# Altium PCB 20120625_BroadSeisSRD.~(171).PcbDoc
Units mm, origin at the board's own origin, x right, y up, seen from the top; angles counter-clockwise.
Board outline 68.5 x 51 mm, 4 copper layers (Top Layer, Mid-Layer 1, Mid-Layer 2, Bottom Layer); 59 components, 42 nets, 186 pads, 37 vias.
Unrouted connection lines stored in the file: 1.
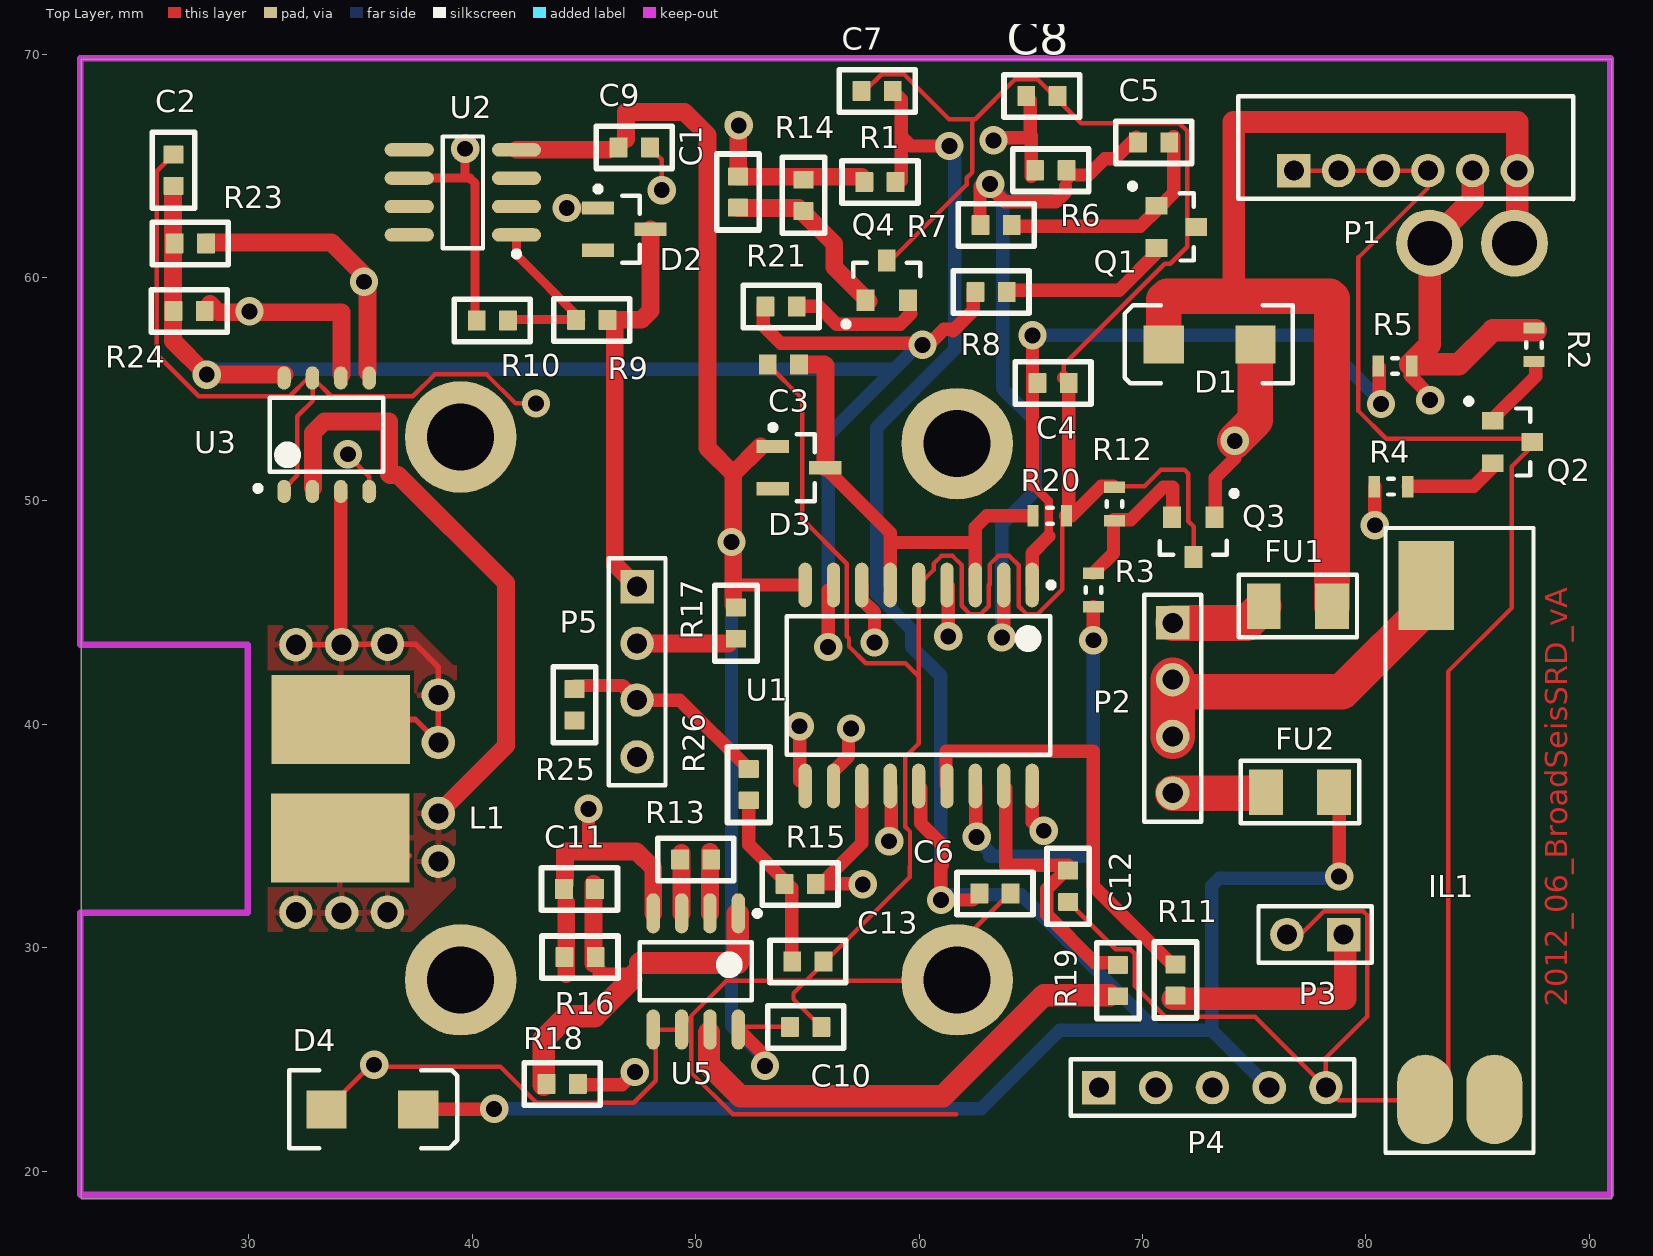
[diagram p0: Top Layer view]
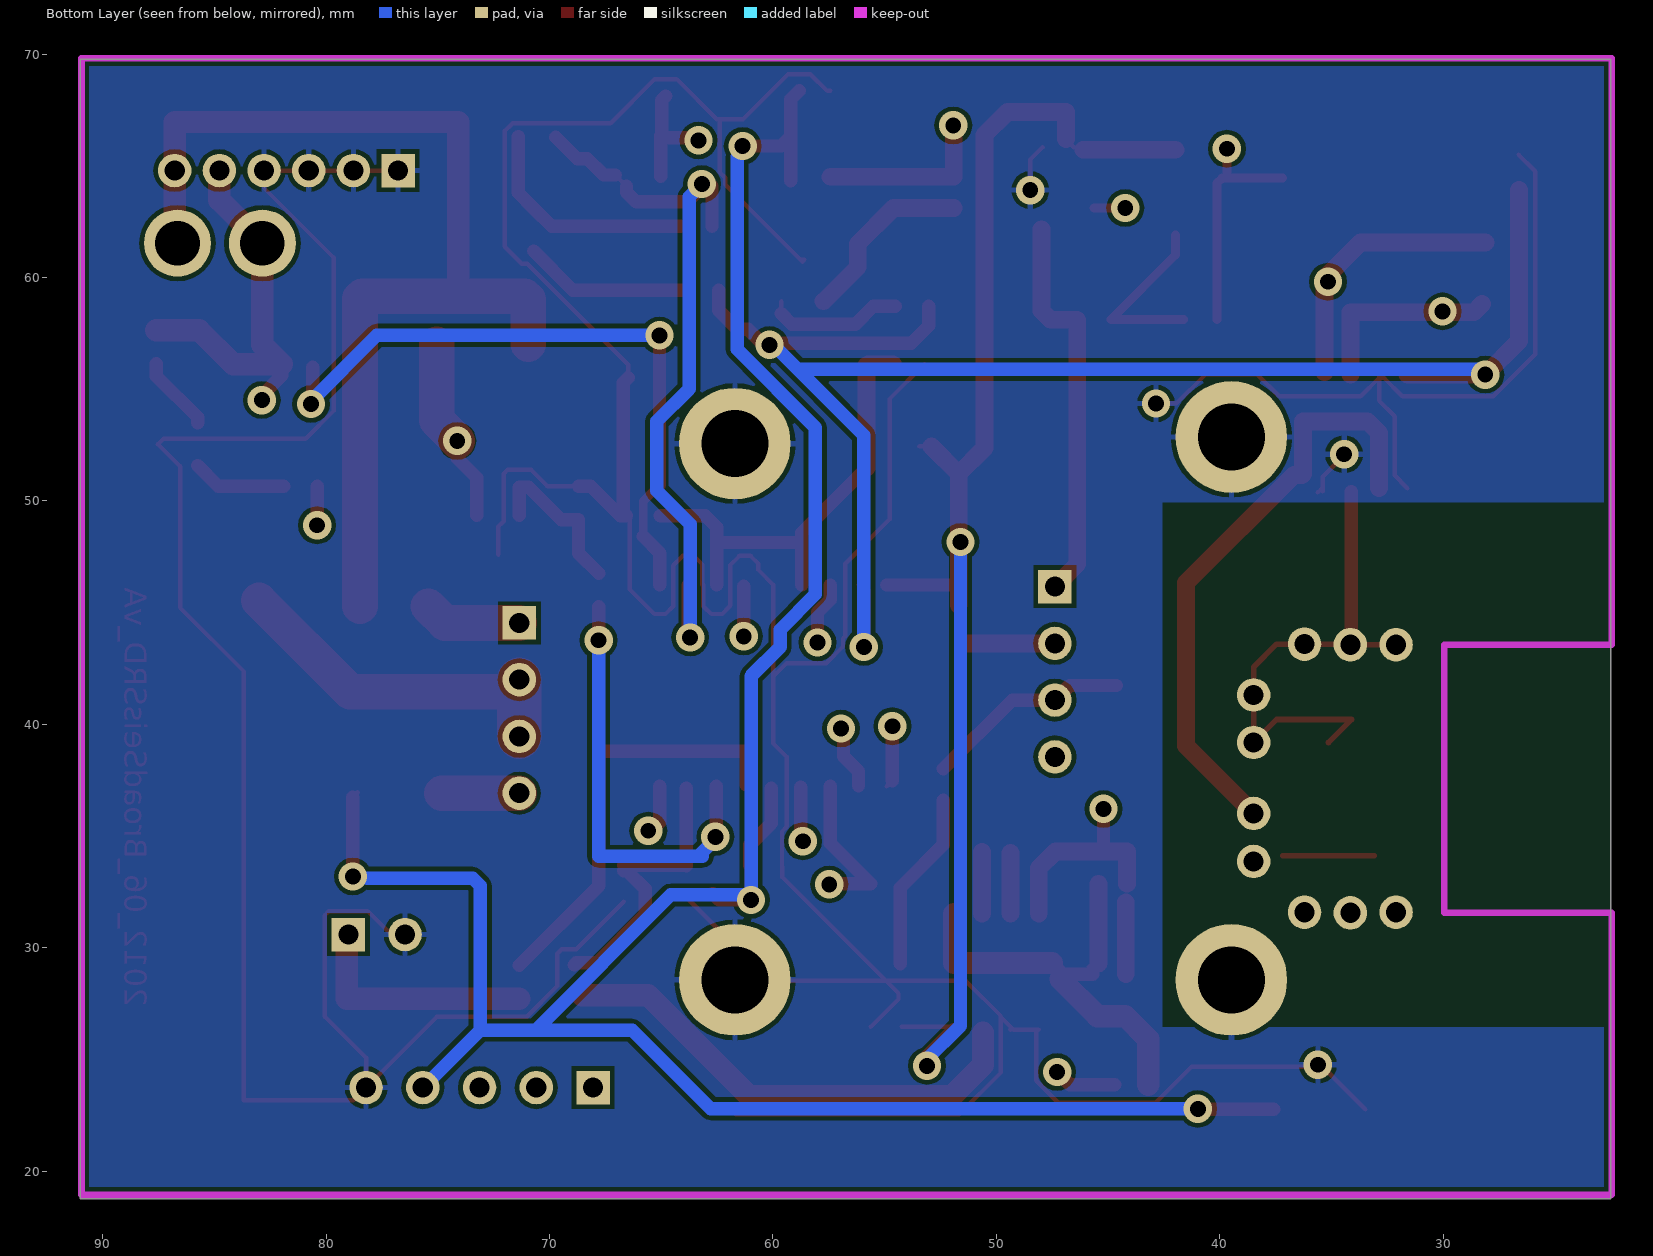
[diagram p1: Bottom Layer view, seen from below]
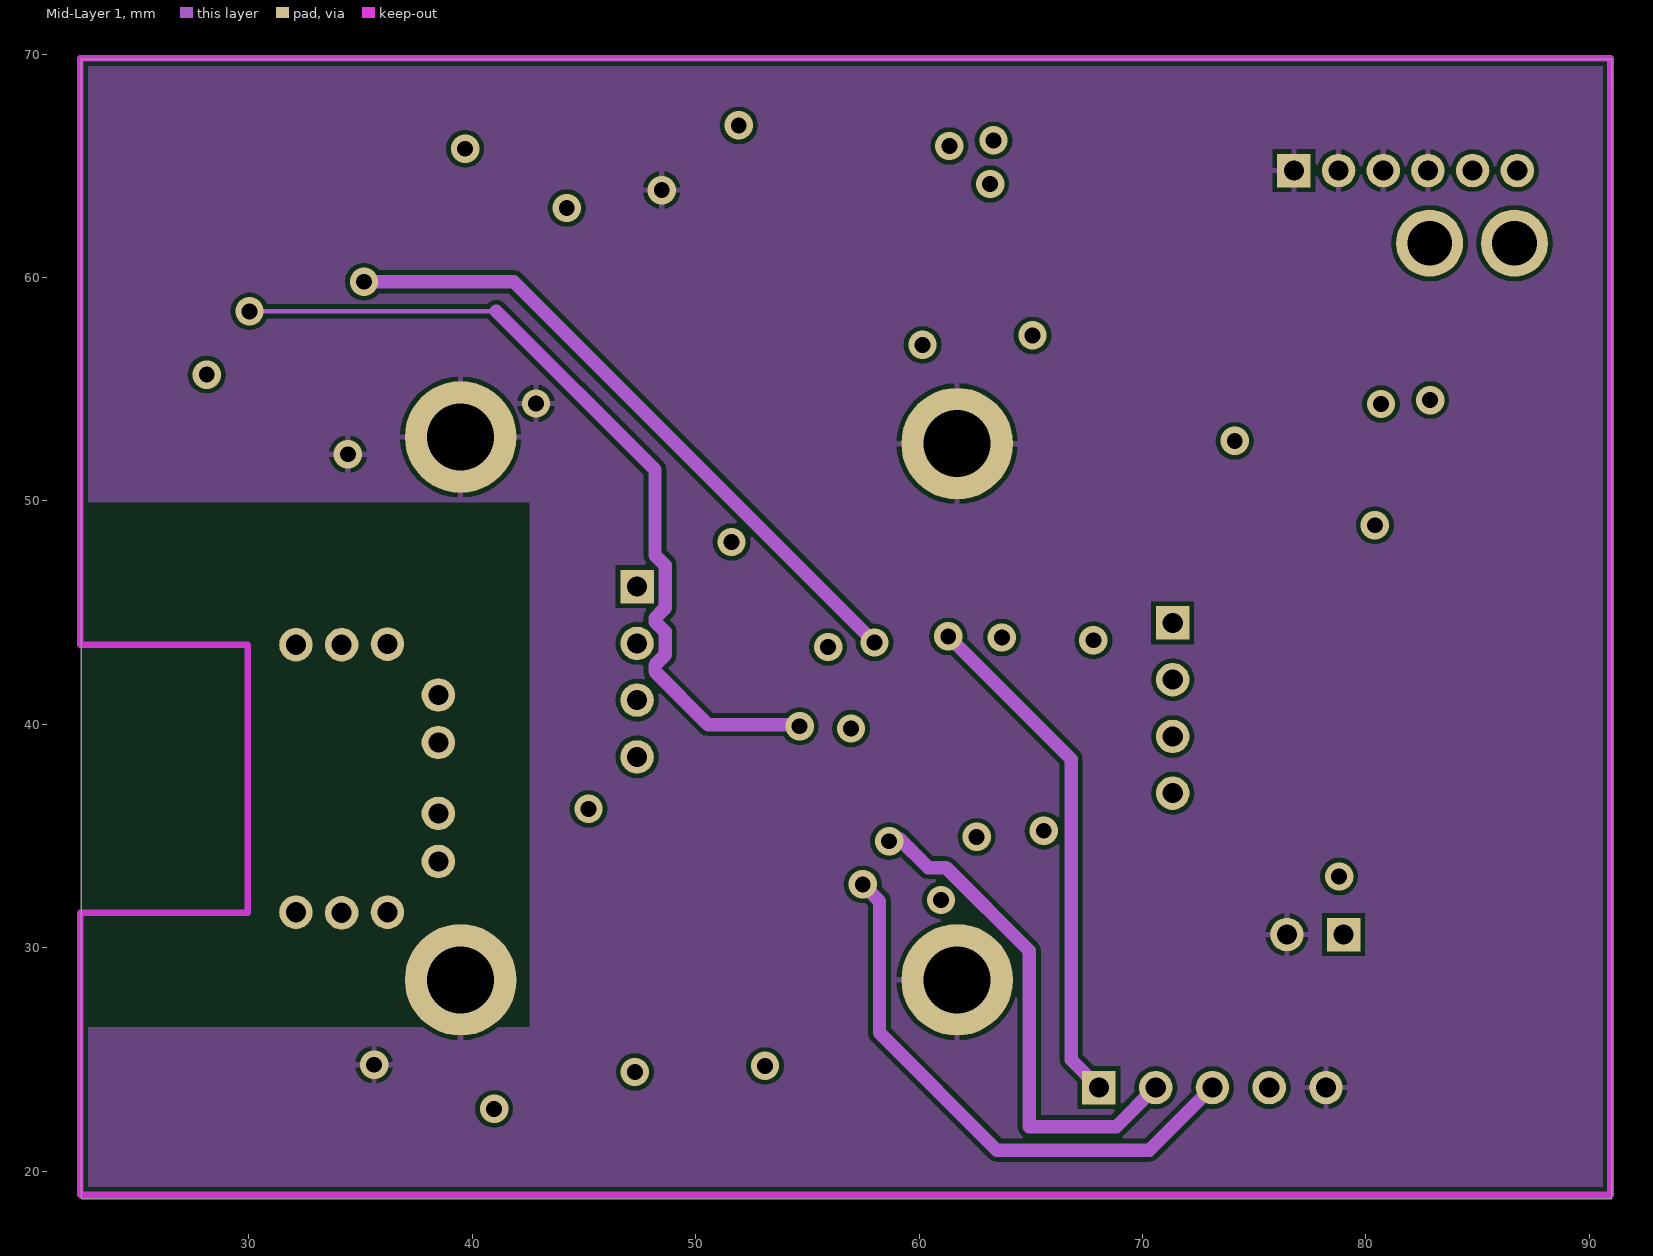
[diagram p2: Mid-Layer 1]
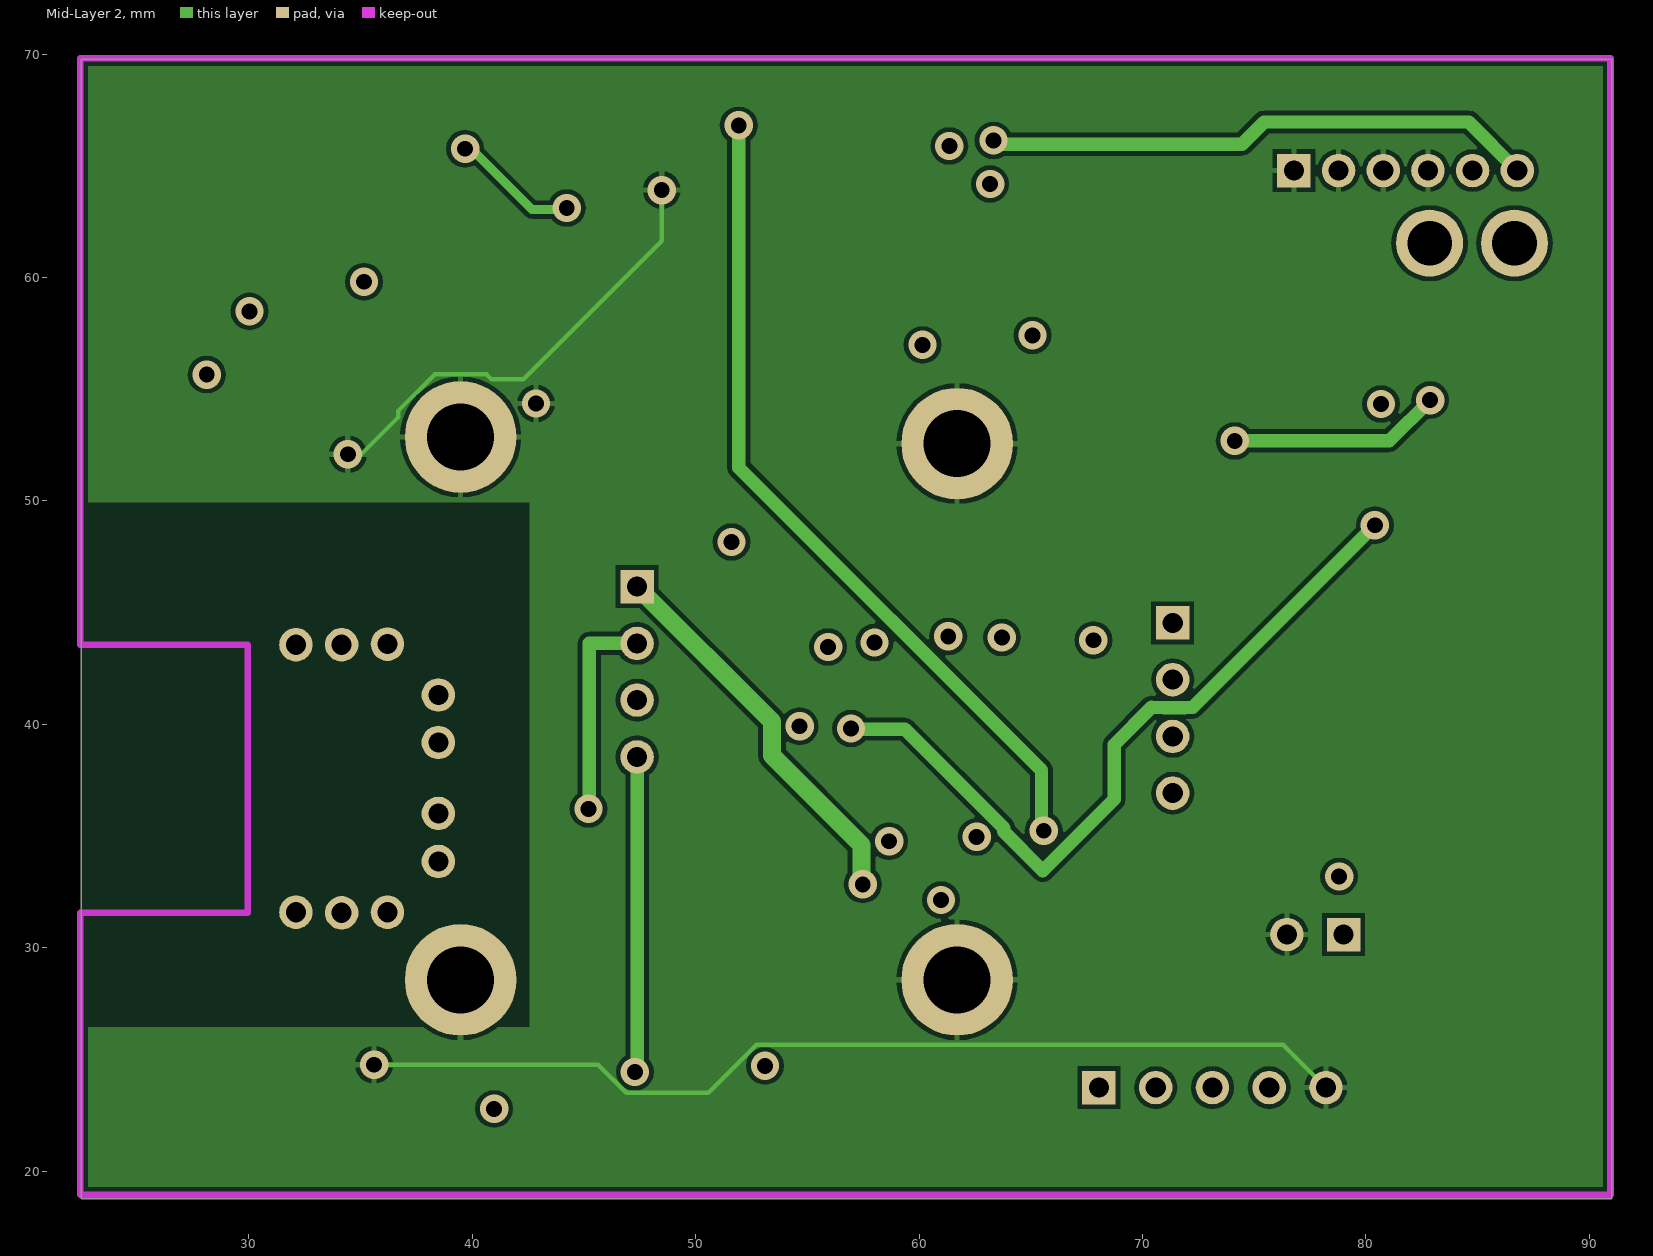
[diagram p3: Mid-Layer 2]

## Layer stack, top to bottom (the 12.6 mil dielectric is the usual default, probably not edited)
Top Layer: signal copper 0.0356
Dielectric: dielectric 0.32, FR-4, Dk 4.8
Mid-Layer 1: signal copper 0.0356
Dielectric: dielectric 0.32, FR-4, Dk 4.8
Mid-Layer 2: signal copper 0.0356
Dielectric: dielectric 0.32, FR-4, Dk 4.8
Bottom Layer: signal copper 0.0356

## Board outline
22.505,18.76 91.005,18.76 91.005,69.76 22.505,69.76

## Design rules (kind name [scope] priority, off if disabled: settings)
Clearance [All] p1: gap=0.2
HoleSize [All] p1: absolutevalues=TRUE maxlimit=5 minlimit=0.025 maxpercent=80.000 minpercent=20.000
PolygonConnect [All] p1: connectstyle=Relief reliefconductorwidth=0.254 reliefentries=4 polygonreliefangle="90 Angle"
RoomDefinition 2012_06_22_Sheet [InComponentClass('2012_06_22_Sheet')] p1: confinementstyle=ConfineIn formatcopy=TRUE lockcomponents=FALSE outline 20.986,71.285 21.117,71.153 93.055,71.153 93.055,17.297 92.819,17.06 20.855,17.06
RoutingVias [All] p1: holewidth=0.6 width=1 viastyle="Through Hole" minholewidth=0.711 minwidth=1.27 maxholewidth=0.711 maxwidth=1.27
SilkscreenOverComponentPads [All] p1: minsilkscreentomaskgap=0.254
SolderMaskExpansion [All] p1: expansion=0.102
Width [All] p1: maxlimit=2 minlimit=0.2 preferedwidth=0.6
26 further rules are at their usual default settings.

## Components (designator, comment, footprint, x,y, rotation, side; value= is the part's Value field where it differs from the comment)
C1 "Cap Semi" 1608[0603]#1 51.9,63.825 r90 top
C2 "Cap Semi" 1608[0603]#1 26.625,64.8 r270 top
C3 "Cap Semi" 1608[0603]#2 53.93,56.11 r0 top
C4 "Cap Semi" 1608[0603]#1 66,55.275 r180 top
C5 "Cap Semi" 1608[0603]#1 70.5,66.05 r180 top
C6 "Cap Semi" 1608[0603]#1 63.4,32.425 r180 top
C7 "Cap Semi" 1608[0603]#1 58.125,68.35 r0 top
C8 "Cap Semi" 1608[0603]#1 65.5,68.125 r180 top
C9 "Cap Semi" 1608[0603]#1 47.25,65.825 r180 top
C10 "Cap Semi" 1608[0603]#1 54.925,26.45 r180 top
C11 "Cap Semi" 1608[0603]#1 44.8,32.625 r180 top
C12 "Cap Semi" 1608[0603]#1 66.675,32.75 r90 top
C13 "Cap Semi" 1608[0603]#1 55.025,29.375 r180 top
D1 "RS1D" DiodeRS1D(recommendedfootprint) 73.005,57.01 r180 top
D2 "Diode BAS16" SOT-23_M 46.805,62.16 r0 top
D3 "Diode BAS16" SOT-23_M 54.63,51.485 r0 top
D4 "RS1D" DiodeRS1D(recommendedfootprint) 35.53,22.76 r0 top
FU1 "1A" FU(recommendedfootprint) 76.955,45.285 r0 top
FU2 "200mA" FU(recommendedfootprint) 77.055,36.96 r180 top
IL1 "ILS" ILS 85.655,46.21 r270 top
L1 "Inductor" INDC4532 34.105,37.56 r270 top
P1 "ConnectorToFB" "HIROSE DF3A-6P" 76.78,64.785 r0 top
P2 "Battery Pack pigtail" HDR1X4 71.355,44.535 r270 top
P3 "Connector to LED" HDR1X2 79.005,30.585 r180 top
P4 "Connector to Prog." HDR1X5 68.055,23.735 r0 top
P5 "Pressure Transducer pigtail" HDR1X4 47.38,46.16 r270 top
Q1 "NPN" transistor_SOT-23(recommendedfootprint) 71.605,62.26 r0 top
Q2 "NPN" transistor_SOT-23(recommendedfootprint) 86.655,52.635 r0 top
Q3 "MOSFET-IRLML" transistor_SOT-23(recommendedfootprint) 72.28,48.285 r270 top
Q4 "NPN" transistor_SOT-23(recommendedfootprint) 58.555,59.96 r90 top
R1 "Res3" J1-0603#1 58.25,64.275 r0 top
R2 "Res3" J1-0603#2 87.53,56.985 r90 top
R3 "Res3" J1-0603#2 67.805,46.01 r90 top
R4 "Res3" J1-0603#2 81.13,50.635 r0 top
R5 "Res3" J1-0603#2 81.305,56.035 r0 top
R6 "Res3" J1-0603#1 65.9,64.8 r180 top
R7 "Res3" J1-0603#1 63.45,62.35 r180 top
R8 "Res3" J1-0603#1 63.225,59.35 r0 top
R9 "Res3" J1-0603#1 45.35,58.1 r0 top
R10 "Res3" J1-0603#1 40.9,58.075 r180 top
R11 "Res3" J1-0603#1 71.475,28.55 r90 top
R12 "Res3" J1-0603#2 68.755,49.86 r270 top
R13 "Res3" J1-0603#1 50,33.95 r0 top
R14 "Res3" J1-0603#1 54.825,63.675 r90 top
R15 "Res3" J1-0603#1 54.675,32.85 r180 top
R16 "Res3" J1-0603#1 44.825,29.575 r180 top
R17 "Res3" J1-0603#1 51.8,44.525 r90 top
R18 "Res3" 1608[0603]#1 44.025,23.9 r180 top
R19 "Res3" J1-0603#1 68.9,28.525 r90 top
R20 "Res3" J1-0603#2 65.855,49.335 r180 top
R21 "Res3" J1-0603#1 53.825,58.7 r0 top
R23 "Res3" J1-0603#1 27.375,61.525 r0 top
R24 "Res3" J1-0603#1 27.325,58.5 r180 top
R25 "Res3" J1-0603#1 44.575,40.875 r90 top
R26 "Res3" J1-0603#1 52.375,37.3 r90 top
U1 "PIC16LF1827-I/SO" SOIC-SO18_L 59.98,41.735 r270 top
U2 "LM334D" SO8_N 39.58,63.81 r180 top
U3 "M24LR64" SO8N_N 33.48,52.96 r90 top
U5 "AD620BR" R-8D_N 50.005,28.935 r270 top

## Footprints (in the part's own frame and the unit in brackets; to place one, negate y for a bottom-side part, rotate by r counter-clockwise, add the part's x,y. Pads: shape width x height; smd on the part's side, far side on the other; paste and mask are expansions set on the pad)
1608[0603]#1 [mm] "Chip Capacitor, Body 1.6x0.8mm, IPC High Density"
  rrect10% 0.8x0.9 smd: 1(-0.7,0) 2(0.7,0)
  silkscreen extent -1.7,-0.95 1.7,0.95
1608[0603]#2 [mm] "Chip Capacitor, Body 1.6x0.8mm, IPC High Density"
  rect 0.8x0.9 smd: 1(-0.7,0) 2(0.7,0)
  body extent -0.87,-0.48 0.87,0.48, height 1.3
DiodeRS1D(recommendedfootprint) [mm] "DO-214-AB/SMC; 2 C-Bend Leads; Body 7.9 x 5.9 mm, inc. leads (LxW)"
  rect 1.8x1.7 smd: 1(-2.05,0) 2(2.05,0)
  silkscreen extent -3.73,-1.75 3.8,1.75
FU(recommendedfootprint) [mm] "Thru-Hole; 2 Leads"
  rect 1.52x2.03 smd: 1(-1.525,0) 2(1.525,0)
  silkscreen extent -2.65,-1.4 2.65,1.4
HDR1X2 [mm] "Connector; Header; 2 Position"
  rect 1.5x1.5 hole 0.9: 1(0,0)
  round 1.5 hole 0.9: 2(2.54,0)
  silkscreen extent -1.27,-1.27 3.81,1.27
HDR1X4 [mm] "Connector; Header; 4 Position"
  rect 1.5x1.5 hole 0.9: 1(0,0)
  round 1.5 hole 0.9: 2(2.54,0) 3(5.08,0) 4(7.62,0)
  silkscreen extent -1.27,-1.27 8.89,1.27
HDR1X5 [mm] "Connector; Header; 5 Position"
  rect 1.5x1.5 hole 0.9: 1(0,0)
  round 1.5 hole 0.9: 2(2.54,0) 3(5.08,0) 4(7.62,0) 5(10.16,0)
  silkscreen extent -1.27,-1.27 11.43,1.27
"HIROSE DF3A-6P" [mm] "Connector; Header; 6 Position"
  rect 1.5x1.5 hole 0.9: 1(0,0)
  round 1.5 hole 0.9: 2(2,0) 3(4,0) 4(6,0) 5(8,0) 6(10,0)
  round 3 hole 2: 5(6.075,-3.25) 6(9.875,-3.25)
  Top Layer lines w0.254: 9.875,-3.25 10,-2.75
  Top Layer lines w1: 6.075,-3.25 8,-1.325 8,0 ; 10,-2.75 10,0
  silkscreen extent -2.5,-1.29 12.5,3.32
ILS [mm]
  rect 4x2.5 smd: 1(0,-2.95)
  oval 4x2.5 smd: 2(23,-3) 3(23,0.1)
  silkscreen extent -2.58,-4.77 25.4,1.85
INDC4532 [mm] "Chip Inductor, Body 4.5x3.2mm, IPC High Density"
  round 1.5 hole 0.9: 1(-6.025,2.1) 1(-6,0.05) 1(-6,-2) 1(-3.75,4.375) 1(-1.625,4.375) 2(1.55,4.375) 2(3.7,4.375) 2(5.975,2.1) 2(5.975,-2) 2(6,0.05)
  rect 4x6.2 smd: 1(-2.65,0) 2(2.65,-0.025)
  Top Layer lines w0.254: -6,-2 -6,0.01 -6,0.05 -6.025,0.075 -6.025,2.1 -6.025,3.35 -5,4.375 -3.75,4.375 -1.625,4.375 -2.65,3.35 -2.65,0 -1.625,1.025
J1-0603#1 [mm] "Chip Capacitor, Body 1.6x0.8mm, IPC High Density"
  rrect10% 0.8x0.9 smd: 1(-0.7,0) 2(0.7,0)
  silkscreen extent -1.7,-0.95 1.7,0.95
J1-0603#2 [mm] "Chip Resistor, Body 1.6x0.8mm, IPC High Density"
  rect 0.5x0.95 smd: 1(-0.75,0) 2(0.75,0)
  silkscreen extent -0.13,-0.35 0.13,0.35, body extent -0.85,-0.48 0.85,0.48, height 0.9
R-8D_N [mm] "SOIC, 8-Leads, Body 4.9x3.9mm, Pitch 1.27mm, IPC Medium Density"
  oval 1.8x0.6 smd: 1(-2.6,1.905) 2(-2.6,0.635) 3(-2.6,-0.635) 4(-2.6,-1.905) 5(2.6,-1.905) 6(2.6,-0.635) 7(2.6,0.635) 8(2.6,1.905)
  silkscreen extent -2.72,-2.5 1.3,2.88, body extent -2,-2.5 2,2.5, height 2.59
SO8_N [mm] "SOIC, 8-Leads, Body 4.9x3.9mm, Pitch 1.27mm, IPC Medium Density"
  oval 2.2x0.6 smd: 1(-2.4,1.905) 2(-2.4,0.635) 3(-2.4,-0.635) 4(-2.4,-1.905) 5(2.4,-1.905) 6(2.4,-0.635) 7(2.4,0.635) 8(2.4,1.905)
  silkscreen extent -2.53,-2.5 0.9,2.88, body extent -1.95,-2.45 1.95,2.45, height 1.75
SO8N_N [mm] "SOP, 8-Leads, Body 5.3x5.3mm, Pitch 1.27mm, IPC Medium Density"
  oval 1.04x0.6 smd: 1(-2.54,1.905) 2(-2.54,0.635) 3(-2.54,-0.635) 4(-2.54,-1.905) 5(2.54,-1.905) 6(2.54,-0.635) 7(2.54,0.635) 8(2.54,1.905)
  silkscreen extent -2.52,-2.54 1.65,3.2, body extent -2.29,-2.54 2.29,2.54, height 2.13
SOIC-SO18_L [mm] "SOIC, 18-Leads, Body 11.5x7.5mm, Pitch 1.27mm, IPC High Density"
  oval 2x0.6 smd: 1(-4.5,5.08) 2(-4.5,3.81) 3(-4.5,2.54) 4(-4.5,1.27) 5(-4.5,0) 6(-4.5,-1.27) 7(-4.5,-2.54) 8(-4.5,-3.81) 9(-4.5,-5.08) 10(4.5,-5.08) 11(4.5,-3.81) 12(4.5,-2.54) 13(4.5,-1.27) 14(4.5,0) 15(4.5,1.27) 16(4.5,2.54) 17(4.5,3.81) 18(4.5,5.08)
  silkscreen extent -4.62,-5.9 3.1,6.06, body extent -3.8,-5.95 3.8,5.95, height 2.65
SOT-23_M [mm] "SOT23, 3-Leads, Body 2.9x1.3mm, Pitch 0.95mm, Lead Span 2.5mm, IPC Low Density"
  rect 1.45x0.6 smd: 1(-1.175,0.95) 2(-1.175,-0.95) 3(1.175,0)
  silkscreen extent -1.3,-1.5 0.7,1.92, body extent -0.7,-1.5 0.7,1.5, height 1.1
transistor_SOT-23(recommendedfootprint) [mm] "SOT23, 3-Leads, Body 2.9x1.3mm, Pitch 0.95mm, Lead Span 2.5mm, IPC Low Density"
  rect 0.972x0.802 smd: 1(-0.975,0.95) 2(-0.975,-0.95) 3(0.8,0)
  silkscreen extent -2.17,-1.5 0.7,1.95, body extent -0.7,-1.5 0.7,1.5, height 1.1

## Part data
C1 C2 C3 C4 C5 C6 C7 C8 C9 C10 C11 C12 C13: "Capacitor (Semiconductor SIM Model)"
D1 D4: library part Diode, "Default Diode"
D2 D3: "Silicon Switching Diode for High-Speed Switching"
FU1 FU2: library part "Fuse 1", "Fuse"
IL1: "SPDT Subminiature Toggle Switch, Right Angle Mounting, Vertical Actuation"
P1: "Header, 6-Pin"
P2 P5: "Header, 4-Pin"
P3: "Header, 2-Pin"
P4: "Header, 5-Pin"
Q1 Q2 Q4: "NPN Bipolar Transistor"
Q3: "N-Channel MOSFET"
R1 R2 R3 R4 R5 R6 R7 R8 R9 R10 R11 R12 R13 R14 R15 R16 R17 R18 R19 R20 R21 R23 R24 R25 R26: "Resistor"
U1: "EPROM-Based 8-Bit CMOS Microcontroller, 25 Bytes RAM, 4 MHz, 18-Pin SOIC, 3.0 to 5.5V Supply Range, Extended Temperature"
U2: "Three Terminal Adjustable Current Source"
U3: "32 Kbit Serial I²C Bus EEPROM"
U5: "Low-Cost, Low-Power Instrumentation Amplifier"

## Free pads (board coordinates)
  round 5 hole 3: 1(39.48,28.56) 1(39.48,52.86) 1(61.705,28.56) 1(61.705,52.56)

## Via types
v1: diameter 1.27, hole 0.711, Top Layer to Bottom Layer, 37 vias

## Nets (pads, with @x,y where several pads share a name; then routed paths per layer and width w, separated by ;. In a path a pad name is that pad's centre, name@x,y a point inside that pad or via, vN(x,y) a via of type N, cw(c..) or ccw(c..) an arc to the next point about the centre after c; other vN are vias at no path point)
ACTIVATION+: FU1.1 P2.1 | length 4.4
  Top Layer w1.6: P2.1 74.68,44.535 FU1.1
ANA_PRESSURE: C12.2 R19.2 U1.17 | length 13.1
  Top Layer w0.2: U1.17 U1.17@63.88,37.145 ; 63.88,33.66 63.905,33.685 ; C12.2@66.675,33.301 C12.2
  Top Layer w0.6: 63.88,33.66 U1.17@63.88,37.145 ; 63.905,33.685 C12.2@66.675,33.685 ; C12.2 66.541,33.45 65.725,32.634 65.725,31.466 67.866,29.325 68.8,29.325 R19.2
B7: P4.2 U1.13 | length 25.1
  Top Layer w0.2: U1.13 U1.13@58.755,37.19
  Top Layer w0.6: v1(58.659,34.764) 58.659,35.014 58.755,35.11 U1.13@58.755,37.19
  Mid-Layer 1 w0.6: v1@58.655,34.885 59.105,34.885 60.405,33.585 61.205,33.585 64.93,29.86 64.93,21.985 68.82,21.985 P4.2@70.583,23.747
CHECK-FIRE: R4.1 U1.11 | length 38.6
  Top Layer w0.2: v1@56.84,39.695 v1(56.955,39.81)
  Top Layer w0.6: U1.11 56.17,37.9 56.84,38.57 v1@56.84,39.695 ; v1(80.405,48.91) R4.1@80.405,50.66
  Mid-Layer 2 w0.6: v1@57.03,39.785 59.36,39.785 63.79,35.355 63.79,35.2 65.543,33.447 68.73,36.635 68.73,39.085 70.405,40.76 70.967,40.735 71.892,40.735 72.255,40.76 v1(80.405,48.91)
COIL1: L1.1 U3.3 | length 6.8
  Top Layer w0.6: L1.1@34.115,43.6 U3.3
COIL2: L1.2 U3.2 | length 31.4
  Top Layer w0.2: 32.87,53.05 32.905,53.085
  Top Layer w0.254: L1.2@33.08,34.11 37.18,34.11
  Top Layer w0.8: U3.2@32.87,50.57 32.87,53.05 ; 32.905,53.085 33.38,53.56 36.28,53.56 36.28,51.193 36.31,51.163 36.677,51.163 41.505,46.335 41.505,39.035 L1.2@38.48,36.01
FB1: C8.2 D1.2 FU1.2 P1.6 R6.2 | length 77
  Top Layer w0.2: 70.955,59.01 71.105,59.16 ; 74.03,59.16 74.08,59.21 ; 78.38,59.16 78.48,59.06
  Top Layer w0.6: v1(63.33,66.135) 63.155,66.135 63.08,66.06 63.305,66.06 63.505,66.26 64.98,66.26 64.98,67.945 C8.2 ; R6.2@65.03,64.535 65.03,66.335
  Top Layer w1: 74.08,59.21 74.08,66.96 86.78,66.96 P1.6@86.78,64.785
  Top Layer w1.6: D1.2 70.955,59.01 ; 71.105,59.16 74.03,59.16 78.38,59.16 ; FU1.2 78.48,59.06
  Mid-Layer 2 w0.6: v1@63.355,66.335 63.73,65.96 74.455,65.96 75.455,66.96 84.605,66.96 P1.6@86.78,64.785
FB2: D1.1 P1.5 Q3.1 R2.2 R5.2 | length 31.7
  Top Layer w0.6: Q3.1@73.255,49.36 73.255,51.035 74.13,51.91 v1(74.13,52.685) ; R5.2@81.98,56.11 81.98,55.61 v1@82.88,54.71
  Top Layer w1: P1.5@82.855,61.535 82.855,56.985 81.98,56.11 84.155,56.11 85.68,57.635 R2.2@87.605,57.635
  Top Layer w1.6: v1(74.13,52.685) 75.055,53.61 D1.1
  Mid-Layer 2 w0.6: v1(74.13,52.685) 81.055,52.685 v1(82.88,54.51)
FIRE: R3.1 U1.16 | length 19.8
  Top Layer w0.2: U1.16 U1.16@62.53,37.225
  Top Layer w0.6: U1.16@62.53,37.225 62.53,34.71 62.605,34.785 62.655,34.785 62.58,34.86 v1(62.58,34.96) ; v1(67.805,43.76) R3.1
  Bottom Layer w0.6: v1@62.53,34.71 62.605,34.785 62.655,34.785 63.28,34.16 ; 63.155,34.085 67.805,34.085 v1(67.805,43.76)
FLASH_LED: R11.2 U1.15 | length 19.2
  Top Layer w0.2: U1.15@61.205,37.28 U1.15
  Top Layer w0.6: U1.15@61.205,37.28 61.205,38.785 67.805,38.785 67.805,32.76 R11.2@71.355,29.21
GND: C2.1 C3.1 C4.1 C6.1 C7.1 C8.1 C9.1 C10.1 C12.1 C13.1 D4.1 IL1.2 P1.1 P1.2 P1.3 P1.4 P3.2 P4.5 pad.1 Q1.3 Q2.3 Q3.3 Q4.3 R12.1 R20.1 R25.1 U1.5 U3.1 U3.4 U3.7 U5.5 U5.6 | length 362.8
  Top Layer w0.2: C2.1 25.875,64.75 25.875,56.568 27.763,54.68 31.824,54.68 32.644,55.5 U3.7 ; U3.1@31.6,50.57 32.17,51.14 32.17,53.785 32.87,54.485 U3.7@32.87,55.5 ; U3.7@32.87,55.65 U3.7@32.87,55.5 ; D4.1 35.392,24.672 41.261,24.672 42.874,23.06 47.227,23.06 48.215,24.048 48.215,26.22 U5.5 49.24,26.335 U5.6@49.305,26.4 ; v1@34.28,51.885 34.58,51.885 35.385,51.08 U3.4 ; U3.4@35.41,50.57 U3.4@35.605,50.375 ; v1(42.855,54.36) 41.94,54.36 40.64,55.66 38.32,55.66 37.34,54.68 33.69,54.68 U3.7@32.87,55.5 ; C9.1@47.93,65.835 48.48,65.285 v1(48.48,63.91) ; U5.6 U5.6@49.305,26.4 ; C3.1 54.78,54.56 54.78,49.173 56.77,47.184 56.77,43.942 56.865,43.847 56.865,43.478 57.618,42.725 59.39,42.725 59.98,42.135 ; C10.1 54.38,27.695 54.38,27.96 54.93,28.51 ; C7.1 57.574,68.35 58.324,69.1 59.326,69.1 61.341,67.085 62.375,67.085 ; Q4.3@58.68,60.71 58.605,60.785 58.755,60.785 62.13,64.16 62.13,64.457 62.375,64.702 62.375,67.085 ; 61.671,22.55 51.659,22.55 49.796,24.413 49.796,26.891 ; C6.1@63.78,32.36 C6.1@63.88,32.26 ; C6.1@64.256,32.26 C6.1@63.88,32.26 ; C4.1@66.48,55.51 66.48,56.091 70.998,60.609 71.24,60.609 72.005,61.374 72.005,66.559 71.654,66.91 67.266,66.91 65.301,68.875 64.299,68.875 62.509,67.085 62.375,67.085 ; C12.1 68.8,29.925 69.451,29.925 69.65,29.726 69.65,28.284 71.024,26.91 75.04,26.91 P4.5 ; R20.1@66.705,49.485 66.555,49.335 66.405,49.185 66.405,46.031 65.309,44.935 64.811,44.935 64.46,45.286 64.46,47.114 64.039,47.535 63.541,47.535 63.155,47.149 63.155,46.235 63.12,46.235 63.12,45.286 62.769,44.935 62.271,44.935 61.905,45.301 61.905,47.129 61.499,47.535 61.001,47.535 60.65,47.184 60.65,46.905 U1.5 59.98,42.135 ; R12.1@68.705,50.66 70.094,50.66 70.83,51.396 71.88,51.396 72.056,51.22 72.056,49.084 72.305,48.835 Q3.3@72.305,47.585 ; P3.2 77.081,30.585 78.131,31.635 79.879,31.635 80.055,31.459 80.055,26.91 78.215,25.07 P4.5 ; P1.1 P1.2 P1.3 P1.4 82.78,64.006 79.67,60.896 79.67,54.023 80.909,52.784 87.281,52.784 87.53,52.535 86.541,51.546 86.541,45.221 83.68,42.36 83.68,23.16 78.79,23.16 P4.5 ; U5.6@49.305,26.4 49.796,26.891 ; 49.796,26.891 49.796,26.939 51.366,28.51 54.93,28.51 ; 54.93,28.51 59.58,33.16 59.58,33.635 59.594,33.649 59.594,35.197 59.38,35.411 59.38,38.535 59.98,39.135 59.98,42.135 ; 54.93,28.51 60.13,28.51 C6.1@63.88,32.26
  Top Layer w0.6: C4.1@66.48,55.51 66.705,55.285 R20.1@66.705,49.485 ; R20.1@66.555,49.335 66.83,49.335 68.155,50.66 R12.1@68.705,50.66
  Mid-Layer 2 w0.2: v1@34.28,51.885 34.58,51.885 34.705,51.76 36.68,53.735 36.68,54.02 38.32,55.66 40.64,55.66 40.865,55.435 42.28,55.435 48.48,61.635 v1(48.48,63.91) v1@48.48,64.21 ; v1(35.605,24.76) 45.633,24.76 46.893,23.5 50.573,23.5 52.718,25.645 76.305,25.645 P4.5
  other v1: 34.43,52.085
IN+: D2.3 P4.3 P5.1 R9.2 R15.1 U1.12 | length 67.5
  Top Layer w0.2: v1@57.455,32.86 v1(57.48,32.835)
  Top Layer w0.6: U1.12 57.44,34.67 55.63,32.86 v1@57.455,32.86
  Top Layer w0.8: P5.1 46.38,47.16 46.38,58.11 47.58,58.11 47.98,58.51 D2.3
  Mid-Layer 1 w0.6: v1(57.48,32.835) 58.23,32.085 58.23,26.185 63.48,20.935 70.31,20.935 P4.3@73.123,23.747
  Mid-Layer 2 w0.8: P5.1 53.42,40.12 53.42,38.598 57.424,34.594 57.424,32.891 v1(57.48,32.835)
IN-: P5.3 R25.2 R26.2 | length 9.3
  Top Layer w0.6: R25.2@44.63,41.735 46.725,41.735 P5.3 49.295,41.08 R26.2
LED+: P3.1 R11.1 | length 10.6
  Top Layer w1: R11.1@71.355,27.71 79.08,27.71 79.08,30.51 P3.1
LP0-VDD: C2.2 R8.1 R21.1 R23.1 R24.2 U1.8 U3.8 | length 74.1
  Top Layer w0.2: C2.2@26.605,63.91 C2.2@26.755,64.06 ; U1.8@55.93,45.995 U1.8
  Top Layer w0.6: R21.1@53.03,58.71 53.03,57.835 53.805,57.06 60.489,57.06 61.114,57.685 61.446,57.685 61.521,57.61 62.43,58.519 R8.1@62.43,59.435 ; v1(55.93,43.46) U1.8@55.93,45.995
  Top Layer w0.8: C2.2@26.605,63.91 26.605,61.56 26.605,58.96 26.605,57.16 v1(28.115,55.65) U3.8@31.6,55.65
  Bottom Layer w0.2: v1(28.115,55.65) v1@28.35,55.885
  Bottom Layer w0.6: v1@28.35,55.885 58.88,55.885 ; v1(55.93,43.46) 55.93,52.935 v1@60.28,57.285
  other v1: 60.155,56.985
LP1-VDD: C9.2 C10.2 D3.1 R17.2 U1.9 U2.4 U5.8 | length 65.8
  Top Layer w0.2: C9.2@46.53,65.835 C9.2@46.88,66.185 ; 51.68,46.285 51.73,46.235 ; U5.8 52.025,26.45 C10.2 ; D3.1@52.905,52.435 D3.1 ; v1@53.18,25.065 53.18,24.91 53.355,24.735 v1@53.355,24.685
  Top Layer w0.6: 51.73,46.235 U1.9 ; U5.8 v1@53.18,25.065
  Top Layer w0.8: U2.4 46.11,65.715 ; C9.2@46.88,66.185 46.88,67.41 49.505,67.41 50.53,66.385 50.53,52.36 51.68,51.21 ; R17.2@51.68,45.335 51.68,46.285 51.68,51.21 ; D3.1@52.905,52.435 51.68,51.21
  Bottom Layer w0.2: v1@53.18,24.935 v1@53.405,24.71
  Bottom Layer w0.6: v1(51.605,48.16) 51.605,26.51 v1@53.18,24.935
  other v1: 53.105,24.71
MCLR/: P4.1 U1.4 | length 25.3
  Top Layer w0.2: U1.4 U1.4@61.305,46.18
  Top Layer w0.6: v1(61.305,43.935) U1.4@61.305,46.18
  Mid-Layer 1 w0.6: v1(61.305,43.935) 66.805,38.435 66.805,24.985 P4.1
NetC1_1: C1.1 Q4.1 R14.1 | length 8.2
  Top Layer w0.8: C1.1@51.905,63.11 54.605,63.11 56.205,61.51 56.205,60.46 Q4.1@57.73,58.935
NetC3_2: C3.2 D3.3 R20.2 U1.3 U1.6 | length 21.3
  Top Layer w0.2: 55.755,56.11 55.805,56.06
  Top Layer w0.6: D3.3 58.71,48.58 58.71,48.085 ; U1.6 58.71,48.085 ; 62.445,48.135 58.76,48.135 58.71,48.085 ; U1.3 62.52,48.825 63.03,49.335 R20.2@65.055,49.335
  Top Layer w0.8: C3.2 55.755,56.11 ; D3.3 55.805,56.06
NetC5_1: C5.1 Q1.1 R7.1 | length 10.4
  Top Layer w0.6: R7.1@64.13,62.285 69.905,62.285 70.705,63.085 71.405,63.785 C5.1@71.405,66.31
NetC11_1: C11.1 R16.1 R18.2 U5.1 | length 19.8
  Top Layer w0.2: R16.1@45.43,29.285 45.68,29.035
  Top Layer w0.6: 45.68,29.035 45.68,28.81 47.005,28.81 47.505,29.31
  Top Layer w0.8: R16.1@45.43,29.285 C11.1@45.43,32.86
  Top Layer w1: R18.2@43.205,23.86 43.205,25.91 44.23,26.935 45.48,26.935 47.13,28.585 ; 47.505,29.31 51.88,29.31 U5.1@51.88,31.505
NetC13_2: C13.2 R15.2 R26.1 | length 8.1
  Top Layer w0.2: R15.2@54.13,32.86 R15.2@54.305,32.685
  Top Layer w0.6: R26.1 52.375,35.465 52.375,34.615 R15.2@54.13,32.86 ; C13.2@54.305,29.285 R15.2@54.305,32.685
NetD2_1: D2.1 R10.2 U2.6 | length 17.4
  Top Layer w0.4: U2.6 39.895,64.445 40.13,64.21 R10.2@40.13,58.11 ; 39.68,64.52 v1(39.68,65.76) ; v1(44.23,63.11) D2.1
  Mid-Layer 2 w0.4: v1@39.655,65.76 v1(39.68,65.76) 39.955,65.76 42.68,63.035 44.03,63.035 44.055,63.01 v1@44.055,62.985
NetIL1_1: IL1.1 P2.2 P2.3 | length 16.1
  Top Layer w0.2: P2.2 71.89,41.46
  Top Layer w1.6: 71.89,41.46 78.93,41.46 IL1.1@83.005,45.535
  Top Layer w2: P2.3 P2.2
NetQ1_2: Q1.2 R8.2 | length 7.5
  Top Layer w0.6: R8.2@63.93,59.435 68.955,59.435 Q1.2@70.705,61.185
NetQ2_1: Q2.1 R2.1 | length 3.4
  Top Layer w0.6: Q2.1@85.755,53.485 85.755,53.735 87.605,55.585 R2.1@87.605,56.135
NetQ2_2: Q2.2 R4.2 | length 4.2
  Top Layer w0.6: R4.2@81.905,50.66 84.83,50.66 Q2.2@85.755,51.585
NetQ3_2: Q3.2 R3.2 R12.2 | length 7.3
  Top Layer w0.6: R3.2 68.705,47.66 68.705,49.16 69.48,49.16 70.93,50.61 71.355,50.61 Q3.2@71.355,49.36
NetQ4_2: Q4.2 R21.2 | length 6.2
  Top Layer w0.2: 59.63,58.385 Q4.2@59.63,58.935
  Top Layer w0.6: R21.2@54.53,58.71 55.505,58.71 56.305,57.91 59.155,57.91 59.63,58.385
NetR9_1: R9.1 R10.1 U2.1 | length 8.2
  Top Layer w0.4: R10.1@41.63,58.11 44.88,58.11 41.98,61.01 U2.1
NetR13_1: R13.1 U5.3 | length 2.7
  Top Layer w0.8: U5.3 R13.1@49.37,34.245
NetR13_2: R13.2 U5.2 | length 2.8
  Top Layer w0.8: U5.2 R13.2@50.64,34.295
NetR19_1: R19.1 U5.7 | length 21.9
  Top Layer w1: U5.7@50.596,26.201 50.596,24.744 51.99,23.35 61.07,23.35 65.595,27.875 R19.1@68.55,27.875
OUT+: C11.2 P5.2 R16.2 R17.1 U5.4 | length 26.4
  Top Layer w0.6: 45.205,34.43 v1(45.205,36.21)
  Top Layer w0.8: C11.2@44.155,32.86 44.155,34.31 47.355,34.31 48.1,33.565 U5.4 ; 44.205,28.81 44.205,32.035 ; P5.2 R17.1@51.465,43.62
  Mid-Layer 2 w0.2: v1(45.205,36.21) v1@45.24,36.245
  Mid-Layer 2 w0.6: v1@45.24,36.245 45.24,43.62 P5.2
OUT-: P5.4 R18.1 | length 18
  Top Layer w0.2: v1(47.28,24.435) 47.58,24.435 v1@47.43,24.585
  Top Layer w0.6: R18.1@44.705,23.86 46.705,23.86 v1@47.43,24.585
  Mid-Layer 2 w0.2: v1(47.28,24.435) 47.58,24.435 v1@47.38,24.635
  Mid-Layer 2 w0.6: v1@47.38,24.635 P5.4
PCB+: FU2.2 P2.4 | length 3.5
  Top Layer w1.6: P2.4 FU2.2@74.825,36.915
SCLK: R24.1 U1.10 U3.6 | length 50.1
  Top Layer w0.2: U1.10@54.655,37.48 U1.10
  Top Layer w0.6: U1.10@54.655,37.48 v1(54.655,39.91)
  Top Layer w0.8: R24.1@28.255,58.81 28.62,58.445 34.14,58.445 U3.6@34.14,55.65
  Mid-Layer 1 w0.2: v1(30.03,58.485) 41.08,58.485
  Mid-Layer 1 w0.6: 41.08,58.485 48.18,51.385 48.18,47.567 48.63,47.117 48.63,45.203 48.18,44.753 48.18,44.588 48.63,44.138 48.63,43.102 48.18,42.652 48.18,42.36 50.555,39.985 v1@54.855,39.985
SDA: R23.2 U1.7 U3.5 | length 44.1
  Top Layer w0.6: U1.7 57.44,45.575 58.005,45.01 v1(58.005,43.66)
  Top Layer w0.8: R23.2@28.105,61.56 33.705,61.56 35.305,59.96 U3.5@35.305,55.755
  Mid-Layer 1 w0.6: v1(35.155,59.81) 41.855,59.81 v1@57.755,43.91
VBAT1: C1.2 R1.1 R14.2 U1.18 | length 46.9
  Top Layer w0.6: U1.18 65.06,35.605 v1@65.28,35.385
  Top Layer w0.8: v1@51.905,66.585 51.905,64.51 R1.1@57.43,64.51
  Mid-Layer 2 w0.6: v1(51.93,66.81) 51.93,51.485 65.48,37.935 v1@65.48,35.11
  other v1: 65.58,35.235
VBAT2: C5.2 R6.1 R7.2 U1.2 | length 34.9
  Top Layer w0.2: v1@62.73,64.085 62.655,64.16 62.68,64.185 v1(63.18,64.185) v1@63.18,64.035 ; 66.555,64.085 67.055,64.585
  Top Layer w0.6: R7.2@62.73,62.285 v1@62.73,64.085 ; v1@63.18,64.035 63.83,63.385 66.13,63.385 66.555,63.81 66.555,64.085 ; v1(63.705,43.885) 63.79,43.97 U1.2 ; 67.055,64.585 67.58,64.585 68.305,65.31 68.755,65.31 C5.2@69.718,66.272
  Bottom Layer w0.6: v1(63.18,64.185) 63.755,63.61 63.755,55.01 65.205,53.56 65.205,50.46 63.705,48.96 v1(63.705,43.885)
VDD: C6.2 C7.2 D4.2 FU2.1 P4.4 R1.2 U1.14 | length 119
  Top Layer w0.2: v1@40.955,22.76 v1(40.98,22.785) ; U1.14 U1.14@60.08,37.135 ; 60.98,33.635 61.03,33.685 ; FU2.1 FU2.1@78.805,36.735
  Top Layer w0.6: D4.2 v1@40.955,22.76 ; C7.2 59.205,67.97 59.205,66.31 ; R1.2@59.205,64.335 59.205,66.31 ; U1.14@60.08,37.135 60.08,35.56 61.03,34.61 61.03,33.685 ; 60.98,33.635 v1(60.98,32.135) 62.41,32.135 C6.2 ; v1(61.355,65.885) 59.63,65.885 59.205,66.31 ; v1(78.805,33.185) FU2.1@78.805,36.735
  Bottom Layer w0.2: v1(60.98,32.135) v1@60.98,32.36 ; v1(61.355,65.885) 61.13,65.885 v1@61.605,65.41
  Bottom Layer w0.6: v1(40.98,22.785) 62.78,22.785 66.305,26.31 70.625,26.31 ; v1@61.605,65.41 61.605,56.785 58.105,53.285 58.105,45.813 59.68,44.238 59.68,43.46 60.98,42.16 60.98,32.36 64.575,32.36 70.625,26.31 ; P4.4 73.1,26.31 ; 78.155,33.11 73.445,33.11 73.1,32.765 73.1,26.31 ; 70.625,26.31 73.1,26.31
VFIRE: C4.2 R5.1 U1.1 | length 30.6
  Top Layer w0.2: R5.1@80.48,56.11 R5.1@80.605,55.985
  Top Layer w0.4: 65.08,50.71 65.805,49.985 65.805,48.41
  Top Layer w0.6: U1.1 65.06,47.665 65.805,48.41 ; 65.08,50.71 65.08,55.51 v1(65.08,57.41) ; R5.1@80.605,55.985 80.605,54.41 v1(80.68,54.335)
  Bottom Layer w0.6: v1(65.08,57.41) 77.73,57.41 80.68,54.46 v1(80.68,54.335)
pads on no net: D2.2 D3.2 IL1.3 U2.2 U2.3 U2.5 U2.7 U2.8

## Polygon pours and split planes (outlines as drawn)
COIL1 on Top Layer "Top Layer-No Net" (solid, pour order 51): 30.855,44.435 37.355,44.435 37.405,44.385 39.155,42.635 39.305,42.635 39.305,38.085 39.255,38.035 30.855,38.035
COIL2 on Top Layer "Top Layer-No Net" (solid, pour order 53): 30.855,30.71 37.28,30.71 37.33,30.76 39.255,32.685 39.255,32.835 39.255,36.985 39.305,37.035 39.18,36.91 30.855,36.91
GND on Mid-Layer 1 "Top Layer-No Net" (solid, pour order 45): 22.455,69.81 90.955,69.81 90.955,18.935 22.58,18.935 22.58,26.435 42.58,26.435 42.58,49.935 22.58,49.935
GND on Mid-Layer 2 "MidLayer2" (solid, pour order 47): 22.455,69.81 90.955,69.81 90.955,18.935 22.58,18.935 22.58,26.435 42.58,26.435 42.58,49.935 22.58,49.935
GND on Bottom Layer "Top Layer-No Net" (solid, pour order 49): 22.455,69.81 90.955,69.81 90.955,18.935 22.58,18.935 22.58,26.435 42.58,26.435 42.58,49.935 22.58,49.935

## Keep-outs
Keep-Out Layer:
  lines w0.3: 22.455,18.935 22.455,31.56 29.955,31.56 29.955,39.66 29.955,43.56 22.455,43.56 22.455,51.397 22.455,52.422 22.455,60.36 22.455,69.81 90.955,69.81 90.955,18.935 22.58,18.935

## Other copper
Top Layer:
  text "2012_06_BroadSeisSRD_vA" at 89.005,27.36 h1 r90

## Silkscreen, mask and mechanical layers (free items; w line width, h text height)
Drill Drawing:
  text ".LEGEND" at 25.225,71.075 h1.02
  text "Drill Drawing." at 23.25,29.1 h1.02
